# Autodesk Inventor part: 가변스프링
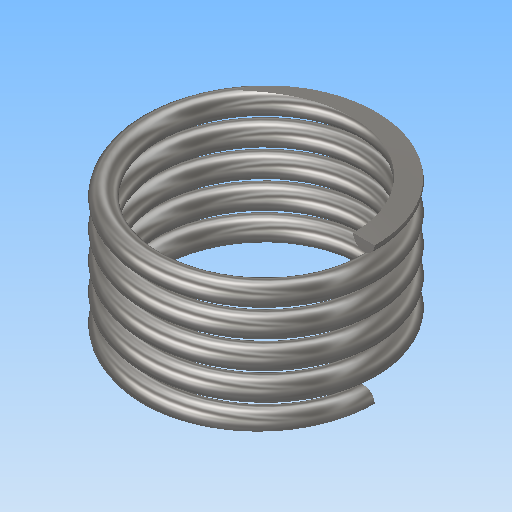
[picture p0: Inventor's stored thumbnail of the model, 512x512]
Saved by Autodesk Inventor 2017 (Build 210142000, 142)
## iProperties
Part Number: 가변스프링
Material: 스테인레스 스틸
Document SubType Name: Modeling
Designer: mrc
Mass: 7.62529 g
Surface Area: 19.5771 cm^2
Volume: 0.953162 cm^3
Density: 8 g/cm^3
Appearance: 반연마
Author: mrc
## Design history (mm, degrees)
sketch "스케치1"
  geometry: L1 (0, 0)-(10, 0); L2 (10, 0)-(10, 12.7); L3 (10, 12.7)-(0, 12.7); L4 (0, 12.7)-(0, 0); C1 r 1 at (10, 0)
  constraints: 8 end point, 2 parallel, 1 centre point, 1 coincident, 1 horizontal, 1 perpendicular
  dimensions: "d0" = 12.7 distance of L1.end L2.end (derived); "d1" = 20 diameter of L2 L4; "d2" = 2 diameter of C1
feature "코일1" sketch "스케치1" pitch "d3" = 10; turns "d5" = 5; dims "d4" = 12.7 (= d0), "d6" = 0, angle "d7" = 90 deg, angle "d8" = 90 deg, "d9" = 0, "d10" = 0
sketch "스케치2"
  geometry: L1 (-17.5, 0)-(17.5, 0); L2 (17.5, 0)-(17.5, 12.7); L3 (17.5, 12.7)-(-17.5, 12.7); L4 (-17.5, 12.7)-(-17.5, 0); 5 further points
  constraints: 8 end point, 2 coincident, 2 horizontal alignment, 2 midpoint, 2 parallel, 1 horizontal, 1 perpendicular
  dimensions: "d11" = 35 distance between parallel lines of L4 L2
extrude "돌출1" sketch "스케치2" stored distance "d12" = 50; taper "d13" = 0 deg
node "솔리드1"
